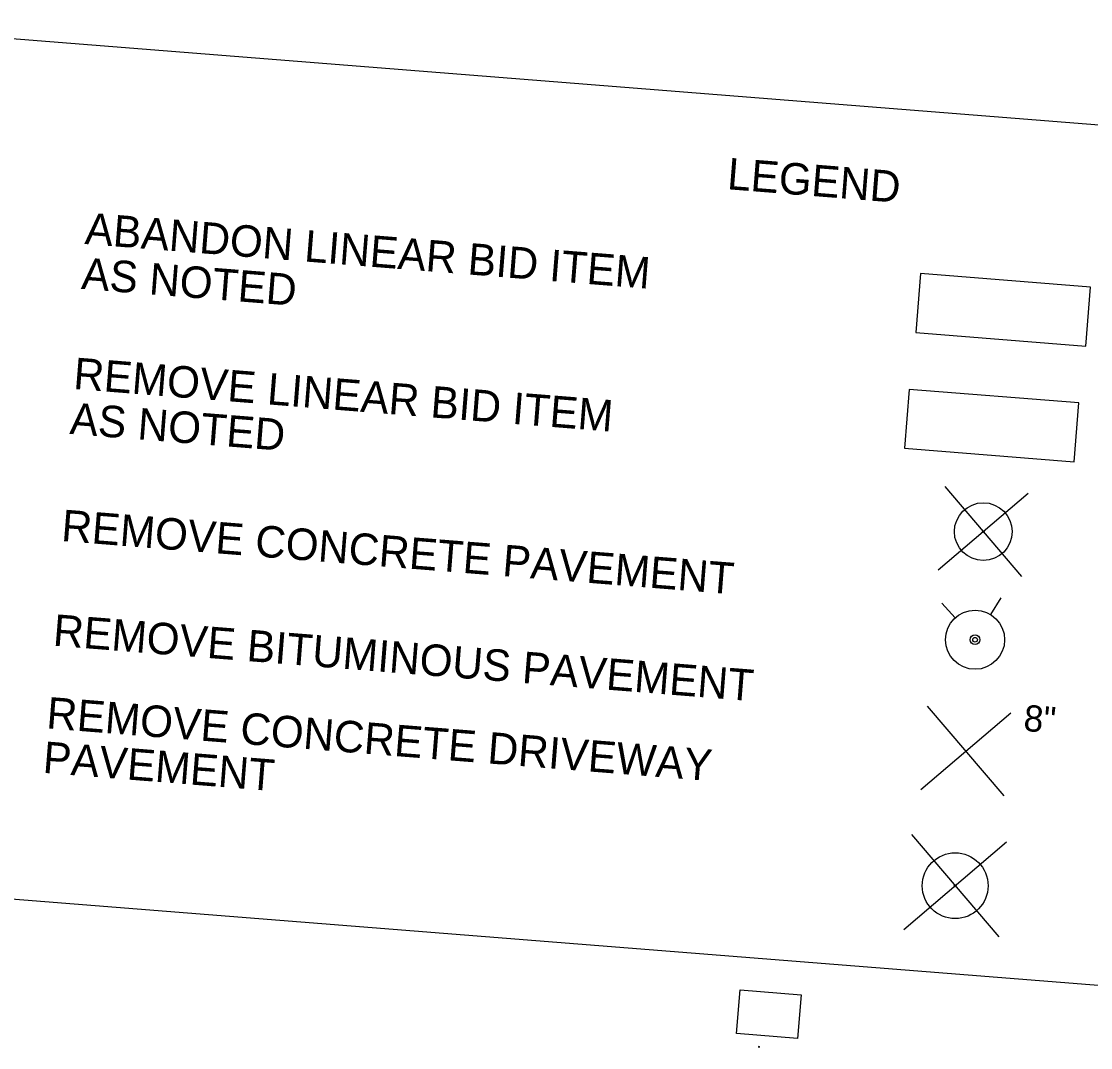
# Model space of a CAD drawing. Extents: x 20499880 to 20505309, y 7953507 to 7955507.
# Drawn here: x 20501408 to 20502629, y 7954334 to 7955507 of the extents above; entities that cross this region are included whole.
import ezdxf

# ---------------------------------------------------------------- set-up
doc = ezdxf.new("R2010")
doc.units = 0
doc.layers.add('Curb', color=7, linetype='Continuous')
doc.layers.add('RowExisting', color=7, linetype='Continuous')

msp = doc.modelspace()

# ---------------------------------------------------------------- linework, layer by layer
at = {"layer": 'Curb'}
for p, q in [((20502249.6, 7954335), (20502251.4, 7954334.9)), ((20502250.4, 7954334), (20502250.5, 7954334.9)), ((20502250.5, 7954334.9), (20502250.6, 7954335.9))]:
    msp.add_line(p, q, dxfattribs=at)
for points in [[(20502229, 7954399.9), (20502298.6, 7954394.4), (20502294.6, 7954344.5), (20502225, 7954350)], [(20502229, 7954399.9), (20502298.6, 7954394.4), (20502294.6, 7954344.5), (20502225, 7954350)], [(20502298.6, 7954394.4), (20502294.6, 7954344.5), (20502225, 7954350), (20502229, 7954399.9)]]:
    msp.add_lwpolyline(points, close=True, dxfattribs=at)
at = {"layer": 'RowExisting'}
for p, q in [((20502455.4, 7954879.8), (20502558.2, 7954967.4)), ((20502463, 7954975), (20502550.6, 7954872.3)), ((20502526.7, 7954848.1), (20502515, 7954828.9)), ((20502459.5, 7954841.7), (20502474.7, 7954825.1)), ((20502530.7, 7954621.6), (20502443.1, 7954724.3)), ((20502435.5, 7954629.1), (20502538.2, 7954716.7)), ((20502424.8, 7954577.6), (20502524.6, 7954460.5)), ((20502416.2, 7954469.1), (20502533.3, 7954569))]:
    msp.add_line(p, q, dxfattribs=at)
for points in [[(20501069.7, 7954530), (20503520.4, 7954335.2), (20503598.2, 7955311.8), (20501147.5, 7955506.6)], [(20502629.1, 7955203), (20502435.2, 7955218.4), (20502429.8, 7955151.1), (20502623.8, 7955135.6)], [(20502616.1, 7955070.7), (20502422.1, 7955086.1), (20502416.8, 7955018.8), (20502610.7, 7955003.4)]]:
    msp.add_lwpolyline(points, close=True, dxfattribs=at)
for centre, radius in [((20502506.8, 7954923.6), 33), ((20502506.8, 7954923.6), 0.989), ((20502497.4, 7954800.1), 33.8), ((20502497.4, 7954800.1), 5.63), ((20502497.4, 7954800.1), 2.7), ((20502474.7, 7954519), 37.6), ((20502474.7, 7954519), 37.6), ((20502474.7, 7954519), 1.13)]:
    msp.add_circle(centre, radius, dxfattribs=at)

# ---------------------------------------------------------------- texts
for s, height, p in [('LEGEND', 36, (20502213.4, 7955314.9)), ('ABANDON LINEAR BID ITEM', 36, (20501479.5, 7955252.3)), ('AS NOTED', 36, (20501475.5, 7955201)), ('REMOVE LINEAR BID ITEM', 36, (20501466.4, 7955086.7)), ('AS NOTED', 36, (20501462.3, 7955035.3)), ('REMOVE CONCRETE PAVEMENT', 36, (20501452.6, 7954913)), ('REMOVE BITUMINOUS PAVEMENT', 36, (20501443.1, 7954793.4)), ('REMOVE CONCRETE DRIVEWAY ', 36, (20501435.6, 7954698.9)), ('8"', 30, (20502552.1, 7954696)), ('PAVEMENT', 36, (20501431.5, 7954648.1))]:
    msp.add_text(s, height=height, rotation=355.4564, dxfattribs=at).set_placement(p)

doc.saveas('drawing.dxf')
